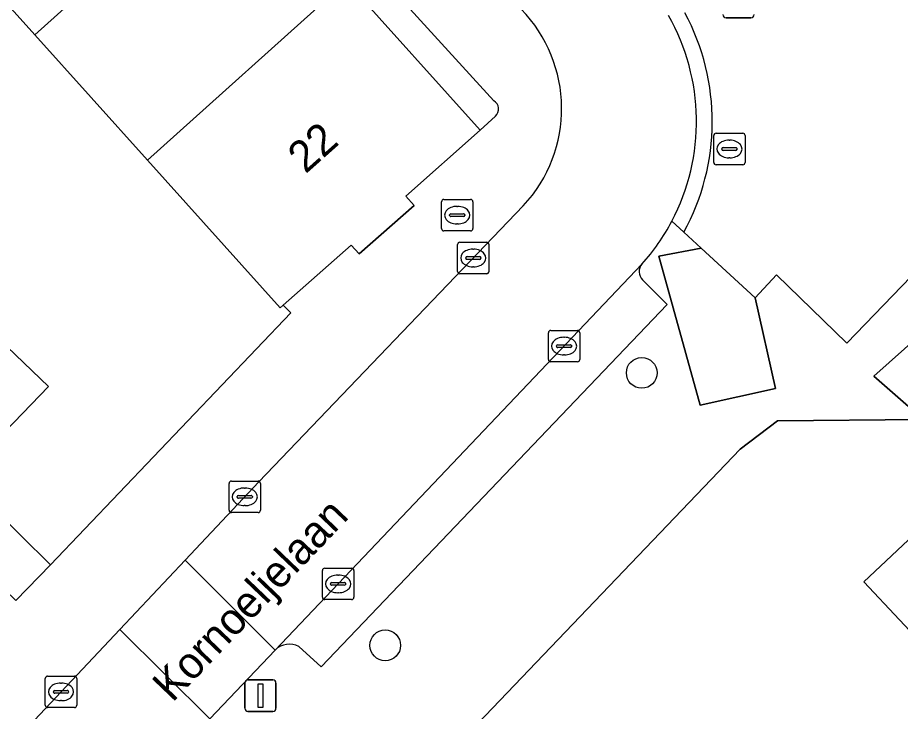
# Model space of a CAD drawing. Extents: x 162344 to 162869, y 381217 to 381818.
# Drawn here: x 162658.91 to 162687, y 381421.83 to 381443.89 of the extents above; entities that cross this region are included whole.
import ezdxf

# ---------------------------------------------------------------- set-up
doc = ezdxf.new("R2010")
doc.units = 0
for name, color, linetype in [('IMGEO_Boom', 7, 'Continuous'), ('IMGEO_Brandkraan', 7, 'Continuous'), ('IMGEO_Erf', 7, 'Continuous'), ('IMGEO_Kolk', 7, 'Continuous'), ('IMGEO_Lichtmast', 7, 'Continuous'), ('IMGEO_Muur', 7, 'Continuous'), ('IMGEO_Openbare_ruimte_label', 7, 'Continuous'), ('IMGEO_Pand', 7, 'Continuous'), ('IMGEO_Pand_nummerreeks', 7, 'Continuous'), ('IMGEO_Parkeervlak_open', 7, 'Continuous'), ('IMGEO_Rijbaan_lokaal_gesloten', 7, 'Continuous'), ('IMGEO_Rijbaan_lokaal_open', 7, 'Continuous'), ('IMGEO_Rioolput', 7, 'Continuous'), ('IMGEO_Terreindeel_open', 7, 'Continuous'), ('IMGEO_Voetpad_open', 7, 'Continuous')]:
    doc.layers.add(name, color=color, linetype=linetype)

msp = doc.modelspace()

# ---------------------------------------------------------------- linework, layer by layer
at = {"layer": 'IMGEO_Boom'}
for centre in [(162678.771, 381432.592), (162670.609, 381423.927)]:
    msp.add_circle(centre, 0.489, dxfattribs=at)
at = {"layer": 'IMGEO_Brandkraan'}
for p, q in [((162672.475, 381438.108), (162673.327, 381438.108)), ((162672.4, 381437.182), (162672.4, 381438.034)), ((162672.888, 381437.888), (162672.913, 381437.888)), ((162673.401, 381438.034), (162673.401, 381437.182)), ((162672.659, 381437.602), (162672.659, 381437.614)), ((162673.097, 381437.565), (162672.699, 381437.565)), ((162672.702, 381437.651), (162673.1, 381437.651)), ((162673.143, 381437.614), (162673.143, 381437.602)), ((162672.911, 381437.328), (162672.886, 381437.328)), ((162673.327, 381437.108), (162672.475, 381437.108))]:
    msp.add_line(p, q, dxfattribs=at)
for points in [[(162672.475, 381438.108), (162673.327, 381438.108)], [(162672.4, 381437.182), (162672.4, 381438.034)], [(162673.401, 381438.034), (162673.401, 381437.182)], [(162673.327, 381437.108), (162672.475, 381437.108)]]:
    msp.add_lwpolyline(points, dxfattribs=at)
for centre, radius, start, end in [((162672.477, 381438.032), 0.0765, 91.552, 178.448), ((162672.477, 381438.032), 0.0765, 91.552, 178.448), ((162673.325, 381438.032), 0.0765, 1.552, 88.448), ((162673.325, 381438.032), 0.0765, 1.552, 88.448), ((162672.699, 381437.611), 0.0403, 85.8775, 175.7526), ((162672.696, 381437.601), 0.0366, 178.938, 274.7102), ((162673.1, 381437.608), 0.043, 264.8664, 352.4533), ((162673.104, 381437.613), 0.0386, 1.7309, 96.639), ((162672.477, 381437.184), 0.0765, 181.552, 268.448), ((162672.477, 381437.184), 0.0765, 181.552, 268.448), ((162673.325, 381437.184), 0.0765, 271.552, 358.448), ((162673.325, 381437.184), 0.0765, 271.552, 358.448)]:
    msp.add_arc(centre, radius, start, end, dxfattribs=at)
for centre, major_axis, ratio, start_param, end_param in [((162672.887, 381437.608), (-0.387, 0.002), 0.722429, 4.712389, 7.853982), ((162672.912, 381437.608), (-0.39, 0.002), 0.717154, 1.570796, 4.712389)]:
    msp.add_ellipse(centre, major_axis=major_axis, ratio=ratio, start_param=start_param, end_param=end_param, dxfattribs=at)
at = {"layer": 'IMGEO_Erf'}
for points in [[(162674.063, 381441.248), (162667.63, 381448.308), (162666.971, 381447.716), (162669.374, 381445.044), (162673.628, 381440.312), (162674.119, 381440.758)], [(162658.04, 381433.93), (162659.894, 381432.164), (162657.12, 381429.282), (162659.964, 381426.485), (162667.609, 381434.502), (162667.366, 381434.744), (162667.269, 381434.658), (162663.05, 381439.352), (162659.46, 381443.343), (162655.467, 381447.783)], [(162690.103, 381415.319), (162687.343, 381418.257), (162690.379, 381421.109), (162685.836, 381425.945), (162689.381, 381429.276), (162687.662, 381431.106), (162683.091, 381431.065), (162681.901, 381430.17), (162662.676, 381410.063), (162654.072, 381401.064), (162653.457, 381400.36)]]:
    msp.add_lwpolyline(points, dxfattribs=at)
msp.add_arc((162673.908, 381440.982), 0.308, 313.2052, 59.8344, dxfattribs=at)
at = {"layer": 'IMGEO_Kolk'}
for p, q in [((162672.91, 381435.819), (162672.91, 381436.671)), ((162672.985, 381436.745), (162673.837, 381436.745)), ((162673.911, 381436.671), (162673.911, 381435.819)), ((162673.398, 381436.525), (162673.423, 381436.525)), ((162673.169, 381436.239), (162673.169, 381436.251)), ((162673.607, 381436.202), (162673.209, 381436.202)), ((162673.212, 381436.288), (162673.61, 381436.288)), ((162673.653, 381436.251), (162673.653, 381436.239)), ((162673.421, 381435.965), (162673.396, 381435.965)), ((162673.837, 381435.745), (162672.985, 381435.745)), ((162675.8, 381433.017), (162675.8, 381433.869)), ((162675.875, 381433.943), (162676.727, 381433.943)), ((162676.801, 381433.869), (162676.801, 381433.017)), ((162676.288, 381433.723), (162676.313, 381433.723)), ((162676.059, 381433.437), (162676.059, 381433.449)), ((162676.497, 381433.4), (162676.099, 381433.4)), ((162676.102, 381433.486), (162676.5, 381433.486)), ((162676.543, 381433.449), (162676.543, 381433.437)), ((162676.311, 381433.163), (162676.286, 381433.163)), ((162676.727, 381432.943), (162675.875, 381432.943)), ((162665.64, 381428.224), (162665.64, 381429.076)), ((162665.715, 381429.15), (162666.567, 381429.15)), ((162666.641, 381429.076), (162666.641, 381428.224)), ((162666.128, 381428.93), (162666.153, 381428.93)), ((162665.899, 381428.644), (162665.899, 381428.656)), ((162666.337, 381428.607), (162665.939, 381428.607)), ((162665.942, 381428.693), (162666.34, 381428.693)), ((162666.383, 381428.656), (162666.383, 381428.644)), ((162666.151, 381428.37), (162666.126, 381428.37)), ((162666.567, 381428.15), (162665.715, 381428.15)), ((162668.611, 381425.455), (162668.611, 381426.307)), ((162668.686, 381426.381), (162669.538, 381426.381)), ((162669.612, 381426.307), (162669.612, 381425.455)), ((162669.099, 381426.161), (162669.124, 381426.161)), ((162668.87, 381425.875), (162668.87, 381425.887)), ((162669.308, 381425.838), (162668.91, 381425.838)), ((162668.913, 381425.924), (162669.311, 381425.924)), ((162669.354, 381425.887), (162669.354, 381425.875)), ((162669.122, 381425.601), (162669.097, 381425.601)), ((162669.538, 381425.381), (162668.686, 381425.381)), ((162659.869, 381422.948), (162660.721, 381422.948)), ((162659.794, 381422.022), (162659.794, 381422.874)), ((162660.282, 381422.728), (162660.307, 381422.728)), ((162660.795, 381422.874), (162660.795, 381422.022)), ((162660.053, 381422.442), (162660.053, 381422.454)), ((162660.491, 381422.405), (162660.093, 381422.405)), ((162660.096, 381422.491), (162660.494, 381422.491)), ((162660.537, 381422.454), (162660.537, 381422.442)), ((162660.305, 381422.168), (162660.28, 381422.168)), ((162660.721, 381421.948), (162659.869, 381421.948))]:
    msp.add_line(p, q, dxfattribs=at)
for points in [[(162672.91, 381435.819), (162672.91, 381436.671)], [(162672.985, 381436.745), (162673.837, 381436.745)], [(162673.911, 381436.671), (162673.911, 381435.819)], [(162673.837, 381435.745), (162672.985, 381435.745)], [(162675.8, 381433.017), (162675.8, 381433.869)], [(162675.875, 381433.943), (162676.727, 381433.943)], [(162676.801, 381433.869), (162676.801, 381433.017)], [(162676.727, 381432.943), (162675.875, 381432.943)], [(162665.64, 381428.224), (162665.64, 381429.076)], [(162665.715, 381429.15), (162666.567, 381429.15)], [(162666.641, 381429.076), (162666.641, 381428.224)], [(162666.567, 381428.15), (162665.715, 381428.15)], [(162668.611, 381425.455), (162668.611, 381426.307)], [(162668.686, 381426.381), (162669.538, 381426.381)], [(162669.612, 381426.307), (162669.612, 381425.455)], [(162669.538, 381425.381), (162668.686, 381425.381)], [(162659.869, 381422.948), (162660.721, 381422.948)], [(162659.794, 381422.022), (162659.794, 381422.874)], [(162660.795, 381422.874), (162660.795, 381422.022)], [(162660.721, 381421.948), (162659.869, 381421.948)]]:
    msp.add_lwpolyline(points, dxfattribs=at)
for centre, radius, start, end in [((162672.987, 381436.669), 0.0765, 91.552, 178.448), ((162672.987, 381436.669), 0.0765, 91.552, 178.448), ((162673.835, 381436.669), 0.0765, 1.552, 88.448), ((162673.835, 381436.669), 0.0765, 1.552, 88.448), ((162673.209, 381436.248), 0.0403, 85.8775, 175.7526), ((162673.206, 381436.238), 0.0366, 178.938, 274.7102), ((162673.61, 381436.245), 0.043, 264.8664, 352.4533), ((162673.614, 381436.25), 0.0386, 1.7309, 96.639), ((162672.987, 381435.821), 0.0765, 181.552, 268.448), ((162672.987, 381435.821), 0.0765, 181.552, 268.448), ((162673.835, 381435.821), 0.0765, 271.552, 358.448), ((162673.835, 381435.821), 0.0765, 271.552, 358.448), ((162675.877, 381433.867), 0.0765, 91.552, 178.448), ((162675.877, 381433.867), 0.0765, 91.552, 178.448), ((162676.725, 381433.867), 0.0765, 1.552, 88.448), ((162676.725, 381433.867), 0.0765, 1.552, 88.448), ((162676.099, 381433.446), 0.0403, 85.8775, 175.7526), ((162676.096, 381433.436), 0.0366, 178.938, 274.7102), ((162676.5, 381433.443), 0.043, 264.8664, 352.4533), ((162676.504, 381433.448), 0.0386, 1.7309, 96.639), ((162675.877, 381433.019), 0.0765, 181.552, 268.448), ((162675.877, 381433.019), 0.0765, 181.552, 268.448), ((162676.725, 381433.019), 0.0765, 271.552, 358.448), ((162676.725, 381433.019), 0.0765, 271.552, 358.448), ((162665.717, 381429.074), 0.0765, 91.552, 178.448), ((162665.717, 381429.074), 0.0765, 91.552, 178.448), ((162666.565, 381429.074), 0.0765, 1.552, 88.448), ((162666.565, 381429.074), 0.0765, 1.552, 88.448), ((162665.939, 381428.653), 0.0403, 85.8775, 175.7526), ((162665.936, 381428.643), 0.0366, 178.938, 274.7102), ((162666.34, 381428.65), 0.043, 264.8664, 352.4533), ((162666.344, 381428.655), 0.0386, 1.7309, 96.639), ((162665.717, 381428.226), 0.0765, 181.552, 268.448), ((162665.717, 381428.226), 0.0765, 181.552, 268.448), ((162666.565, 381428.226), 0.0765, 271.552, 358.448), ((162666.565, 381428.226), 0.0765, 271.552, 358.448), ((162668.688, 381426.305), 0.0765, 91.552, 178.448), ((162668.688, 381426.305), 0.0765, 91.552, 178.448), ((162669.536, 381426.305), 0.0765, 1.552, 88.448), ((162669.536, 381426.305), 0.0765, 1.552, 88.448), ((162668.91, 381425.884), 0.0403, 85.8775, 175.7526), ((162668.907, 381425.874), 0.0366, 178.938, 274.7102), ((162669.311, 381425.881), 0.043, 264.8664, 352.4533), ((162669.315, 381425.886), 0.0386, 1.7309, 96.639), ((162668.688, 381425.457), 0.0765, 181.552, 268.448), ((162668.688, 381425.457), 0.0765, 181.552, 268.448), ((162669.536, 381425.457), 0.0765, 271.552, 358.448), ((162669.536, 381425.457), 0.0765, 271.552, 358.448), ((162659.871, 381422.872), 0.0765, 91.552, 178.448), ((162659.871, 381422.872), 0.0765, 91.552, 178.448), ((162660.719, 381422.872), 0.0765, 1.552, 88.448), ((162660.719, 381422.872), 0.0765, 1.552, 88.448), ((162660.093, 381422.451), 0.0403, 85.8775, 175.7526), ((162660.09, 381422.441), 0.0366, 178.938, 274.7102), ((162660.494, 381422.448), 0.043, 264.8664, 352.4533), ((162660.498, 381422.453), 0.0386, 1.7309, 96.639), ((162659.871, 381422.024), 0.0765, 181.552, 268.448), ((162659.871, 381422.024), 0.0765, 181.552, 268.448), ((162660.719, 381422.024), 0.0765, 271.552, 358.448), ((162660.719, 381422.024), 0.0765, 271.552, 358.448)]:
    msp.add_arc(centre, radius, start, end, dxfattribs=at)
for centre, major_axis, ratio, start_param, end_param in [((162673.397, 381436.245), (-0.387, 0.002), 0.722429, 4.712389, 7.853982), ((162673.422, 381436.245), (-0.39, 0.002), 0.717154, 1.570796, 4.712389), ((162676.287, 381433.443), (-0.387, 0.002), 0.722429, 4.712389, 7.853982), ((162676.312, 381433.443), (-0.39, 0.002), 0.717154, 1.570796, 4.712389), ((162666.127, 381428.65), (-0.387, 0.002), 0.722429, 4.712389, 7.853982), ((162666.152, 381428.65), (-0.39, 0.002), 0.717154, 1.570796, 4.712389), ((162669.098, 381425.881), (-0.387, 0.002), 0.722429, 4.712389, 7.853982), ((162669.123, 381425.881), (-0.39, 0.002), 0.717154, 1.570796, 4.712389), ((162660.281, 381422.448), (-0.387, 0.002), 0.722429, 4.712389, 7.853982), ((162660.306, 381422.448), (-0.39, 0.002), 0.717154, 1.570796, 4.712389)]:
    msp.add_ellipse(centre, major_axis=major_axis, ratio=ratio, start_param=start_param, end_param=end_param, dxfattribs=at)
at = {"layer": 'IMGEO_Lichtmast'}
for p, q in [((162682.245, 381443.888), (162681.455, 381443.888)), ((162681.455, 381443.888), (162682.245, 381443.888)), ((162666.143, 381421.928), (162666.143, 381422.728)), ((162666.143, 381422.728), (162666.143, 381421.928)), ((162666.243, 381422.828), (162667.033, 381422.828)), ((162667.033, 381422.828), (162666.243, 381422.828)), ((162667.133, 381422.728), (162667.133, 381421.928)), ((162667.133, 381421.928), (162667.133, 381422.728)), ((162667.033, 381421.828), (162666.243, 381421.828)), ((162666.243, 381421.828), (162667.033, 381421.828))]:
    msp.add_line(p, q, dxfattribs=at)
msp.add_lwpolyline([(162666.563, 381422.703), (162666.713, 381422.703), (162666.713, 381421.953), (162666.563, 381421.953), (162666.563, 381422.703)], dxfattribs=at)
for centre, start, end in [((162681.455, 381443.988), 180, 270), ((162681.455, 381443.988), 180, 270), ((162682.245, 381443.988), 270, 0), ((162682.245, 381443.988), 270, 0), ((162666.243, 381422.728), 90, 180), ((162666.243, 381422.728), 90, 180), ((162667.033, 381422.728), 0, 90), ((162667.033, 381422.728), 360, 90), ((162666.243, 381421.928), 180, 270), ((162666.243, 381421.928), 180, 270), ((162667.033, 381421.928), 270, 0), ((162667.033, 381421.928), 270, 0)]:
    msp.add_arc(centre, 0.1, start, end, dxfattribs=at)
at = {"layer": 'IMGEO_Muur'}
msp.add_lwpolyline([(162667.366, 381434.744), (162667.609, 381434.502), (162659.964, 381426.485)], dxfattribs=at)
at = {"layer": 'IMGEO_Pand'}
for points in [[(162666.613, 381449.436), (162664.937, 381451.295), (162664.299, 381450.721), (162661.798, 381453.482), (162655.467, 381447.783), (162659.46, 381443.343), (162661.928, 381445.567), (162661.387, 381446.167), (162663.451, 381448.028), (162664.169, 381447.232)], [(162663.05, 381439.352), (162669.374, 381445.044), (162666.971, 381447.716), (162667.63, 381448.308), (162666.613, 381449.436), (162664.169, 381447.232), (162663.451, 381448.028), (162661.387, 381446.167), (162661.928, 381445.567), (162659.46, 381443.343)], [(162663.05, 381439.352), (162667.269, 381434.658), (162667.366, 381434.744), (162669.525, 381436.657), (162669.781, 381436.377), (162671.535, 381437.917), (162671.27, 381438.216), (162673.628, 381440.312), (162669.374, 381445.044)], [(162657.12, 381429.282), (162659.894, 381432.164), (162658.04, 381433.93), (162655.266, 381431.048)]]:
    msp.add_lwpolyline(points, close=True, dxfattribs=at)
msp.add_lwpolyline([(162715.93, 381412.961), (162720.044, 381416.828), (162706.964, 381430.752), (162702.923, 381426.952), (162696.813, 381433.45), (162695.443, 381434.907), (162691.971, 381431.646), (162689.898, 381433.853), (162687.339, 381431.45), (162687.662, 381431.106), (162689.381, 381429.276), (162685.836, 381425.945), (162690.379, 381421.109), (162687.343, 381418.257), (162690.103, 381415.319), (162674.389, 381400.557), (162672.5, 381402.517)], dxfattribs=at)
at = {"layer": 'IMGEO_Parkeervlak_open'}
msp.add_lwpolyline([(162682.379, 381434.977), (162680.664, 381436.556), (162679.317, 381436.302), (162680.632, 381431.561), (162683.023, 381432.097)], close=True, dxfattribs=at)
for points in [[(162678.779, 381436.052), (162667.108, 381423.776)], [(162667.861, 381423.892), (162668.576, 381423.249), (162679.575, 381434.769), (162678.796, 381435.552)]]:
    msp.add_lwpolyline(points, dxfattribs=at)
for centre, radius, start, end in [((162679.045, 381435.811), 0.359, 137.7589, 226.1357), ((162667.563, 381423.325), 0.641, 62.2826, 135.2326)]:
    msp.add_arc(centre, radius, start, end, dxfattribs=at)
at = {"layer": 'IMGEO_Rijbaan_lokaal_gesloten'}
msp.add_lwpolyline([(162675.001, 381437.902), (162666.588, 381429.122), (162664.247, 381426.638), (162667.108, 381423.776), (162678.779, 381436.052)], dxfattribs=at)
msp.add_lwpolyline([(162659.707, 381415.996), (162665.03, 381421.591), (162662.167, 381424.432), (162654.69, 381416.499), (162646.035, 381407.328), (162648.768, 381404.63), (162649.268, 381405.147), (162652.432, 381408.357), (162654.926, 381410.976)], close=True, dxfattribs=at)
for centre, radius, start, end in [((162671.688, 381440.996), 4.534, 316.9573, 44.2512), ((162673.708, 381440.586), 6.805, 332.2275, 29.665), ((162673.76, 381440.563), 6.748, 318.0528, 332.1948)]:
    msp.add_arc(centre, radius, start, end, dxfattribs=at)
at = {"layer": 'IMGEO_Rijbaan_lokaal_open'}
msp.add_lwpolyline([(162680.109, 381437.066), (162680.664, 381436.556), (162682.379, 381434.977), (162683.055, 381435.713), (162685.295, 381433.537), (162694.93, 381443.515), (162699.33, 381448.107), (162694.444, 381452.833)], dxfattribs=at)
msp.add_lwpolyline([(162662.167, 381424.432), (162665.03, 381421.591), (162667.108, 381423.776), (162664.247, 381426.638)], close=True, dxfattribs=at)
msp.add_arc((162673.723, 381440.587), 7.292, 331.1337, 28.2749, dxfattribs=at)
at = {"layer": 'IMGEO_Rioolput'}
for p, q in [((162681.06, 381439.286), (162681.06, 381440.138)), ((162681.135, 381440.212), (162681.987, 381440.212)), ((162682.061, 381440.138), (162682.061, 381439.286)), ((162681.362, 381439.755), (162681.76, 381439.755)), ((162681.548, 381439.992), (162681.573, 381439.992)), ((162681.319, 381439.706), (162681.319, 381439.718)), ((162681.757, 381439.669), (162681.359, 381439.669)), ((162681.803, 381439.718), (162681.803, 381439.706)), ((162681.987, 381439.212), (162681.135, 381439.212)), ((162681.571, 381439.432), (162681.546, 381439.432))]:
    msp.add_line(p, q, dxfattribs=at)
for points in [[(162681.06, 381439.286), (162681.06, 381440.138)], [(162681.135, 381440.212), (162681.987, 381440.212)], [(162682.061, 381440.138), (162682.061, 381439.286)], [(162681.987, 381439.212), (162681.135, 381439.212)]]:
    msp.add_lwpolyline(points, dxfattribs=at)
for centre, radius, start, end in [((162681.137, 381440.136), 0.0765, 91.552, 178.448), ((162681.137, 381440.136), 0.0765, 91.552, 178.448), ((162681.985, 381440.136), 0.0765, 1.552, 88.448), ((162681.985, 381440.136), 0.0765, 1.552, 88.448), ((162681.359, 381439.715), 0.0403, 85.8775, 175.7526), ((162681.764, 381439.717), 0.0386, 1.7309, 96.639), ((162681.356, 381439.705), 0.0366, 178.938, 274.7102), ((162681.76, 381439.712), 0.043, 264.8664, 352.4533), ((162681.137, 381439.288), 0.0765, 181.552, 268.448), ((162681.137, 381439.288), 0.0765, 181.552, 268.448), ((162681.985, 381439.288), 0.0765, 271.552, 358.448), ((162681.985, 381439.288), 0.0765, 271.552, 358.448)]:
    msp.add_arc(centre, radius, start, end, dxfattribs=at)
for centre, major_axis, ratio, start_param, end_param in [((162681.547, 381439.712), (-0.387, 0.002), 0.722429, 4.712389, 7.853982), ((162681.572, 381439.712), (-0.39, 0.002), 0.717154, 1.570796, 4.712389)]:
    msp.add_ellipse(centre, major_axis=major_axis, ratio=ratio, start_param=start_param, end_param=end_param, dxfattribs=at)
at = {"layer": 'IMGEO_Terreindeel_open'}
msp.add_lwpolyline([(162689.898, 381433.853), (162691.959, 381435.825), (162691.039, 381436.835), (162686.152, 381432.488), (162687.339, 381431.45)], close=True, dxfattribs=at)
at = {"layer": 'IMGEO_Voetpad_open'}
for points in [[(162617.48, 381497.935), (162619.438, 381495.925), (162623.107, 381499.381), (162627.975, 381494.211), (162624.32, 381490.769), (162624.818, 381489.816), (162625.117, 381489.484), (162627.423, 381491.558), (162628.17, 381492.223), (162634.659, 381484.876), (162635.981, 381483.41), (162637.412, 381481.823), (162649.711, 381468.182), (162651.417, 381466.29), (162652.435, 381465.161), (162664.937, 381451.295), (162666.613, 381449.436), (162667.63, 381448.308), (162674.063, 381441.248)], [(162681.901, 381430.17), (162683.091, 381431.065), (162687.662, 381431.106), (162687.339, 381431.45), (162686.152, 381432.488), (162691.039, 381436.835), (162691.959, 381435.825), (162689.898, 381433.853), (162691.971, 381431.646), (162695.443, 381434.907), (162696.813, 381433.45), (162702.923, 381426.952), (162706.964, 381430.752), (162700.859, 381437.25), (162694.93, 381443.515), (162685.295, 381433.537), (162683.055, 381435.713), (162682.379, 381434.977), (162683.023, 381432.097), (162680.632, 381431.561), (162679.317, 381436.302), (162680.664, 381436.556), (162680.109, 381437.066), (162679.729, 381437.415)], [(162674.119, 381440.758), (162673.628, 381440.312), (162671.27, 381438.216), (162671.535, 381437.917), (162669.781, 381436.377), (162669.525, 381436.657), (162667.366, 381434.744), (162667.609, 381434.502), (162659.964, 381426.485), (162658.852, 381425.353), (162656.668, 381427.458), (162655.633, 381426.331), (162657.831, 381424.284), (162647.681, 381413.583), (162645.709, 381411.504), (162644.16, 381409.871), (162646.035, 381407.328), (162654.69, 381416.499), (162662.167, 381424.432)], [(162662.167, 381424.432), (162664.247, 381426.638), (162666.588, 381429.122), (162675.001, 381437.902)], [(162679.729, 381437.415), (162680.109, 381437.066)], [(162678.796, 381435.552), (162679.575, 381434.769), (162668.576, 381423.249), (162667.861, 381423.892)], [(162653.457, 381400.36), (162654.072, 381401.064), (162662.676, 381410.063), (162681.901, 381430.17)], [(162658.852, 381425.353), (162659.964, 381426.485), (162657.12, 381429.282)], [(162667.108, 381423.776), (162665.03, 381421.591), (162665.023, 381414.746), (162662.739, 381414.553), (162662.79, 381412.345), (162660.442, 381412.228), (162660.432, 381409.854), (162658.236, 381409.726), (162658.161, 381407.466), (162655.889, 381407.451), (162655.755, 381410.624)]]:
    msp.add_lwpolyline(points, dxfattribs=at)
for centre, radius, start, end in [((162671.688, 381440.996), 4.534, 316.9573, 44.2512), ((162673.708, 381440.586), 6.805, 332.2275, 29.665), ((162673.723, 381440.587), 7.292, 331.1337, 28.2749), ((162673.908, 381440.982), 0.308, 313.2052, 59.8344), ((162673.76, 381440.563), 6.748, 318.0528, 332.1948), ((162679.045, 381435.811), 0.359, 137.7589, 226.1357), ((162667.563, 381423.325), 0.641, 62.2826, 135.2326)]:
    msp.add_arc(centre, radius, start, end, dxfattribs=at)

# ---------------------------------------------------------------- texts
at = {"layer": 'IMGEO_Openbare_ruimte_label'}
msp.add_text('Kornoeljelaan', height=1, rotation=46.2964, dxfattribs=at).set_placement((162663.838, 381422.087))
at = {"layer": 'IMGEO_Pand_nummerreeks'}
msp.add_text('22', height=1, rotation=41.7269, dxfattribs=at).set_placement((162668.073, 381438.902))

doc.saveas('drawing.dxf')
